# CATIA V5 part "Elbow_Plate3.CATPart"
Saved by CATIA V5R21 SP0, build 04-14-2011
Part number: Elbow_Plate3
Bounding box of the stored display mesh (mm): x -31.006 to 10.994, y -8.828 to -3.828, z 272.044 to 322.044
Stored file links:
  F:\教程\Robotic_Arm_Arduino_Kinect\机械臂CAD\Arm_Detailed_Design\Elbow_Plate3.CATPart
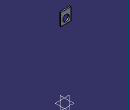
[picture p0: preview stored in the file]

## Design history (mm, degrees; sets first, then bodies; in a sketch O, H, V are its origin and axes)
Body1 (main body)
  DatumSurface1 to DatumSurface4
  Sketch1 on DatumSurface4, origin (0, -8.828, 0), H (-1, 0, 0), V (0, 0, 1)
    line L1 (-10.9938, 322.0436) -> (31.0062, 322.0436)
    line L2 (31.0062, 322.0436) -> (31.0062, 272.0436)
    line L3 (31.0062, 272.0436) -> (-10.9938, 272.0436)
    line L4 (-10.9938, 272.0436) -> (-10.9938, 322.0436)
    circle A1 centre (10.0062, 292.0436) radius 13
    point P5 (10.0062, 292.0436)
    length L1 = 42
    length L2 = 50
    radius A1 = 13
    distance P5 L1 = 30
    distance P5 L2 = 21
    horizontal: L1 H, L3 H
    vertical: L2 V, L4 V
  Pad1: profile Sketch1, direction (0, 1, 0), length 5
  Sketch2 on face of Pad1 from Sketch1.L2, origin (-31.0062, 0, 0), H (0, -1, 0), V (0, 0, 1)
    circle A1 centre (6.328, 307.0436) radius 1.25
    point P1 (6.328, 307.0436)
    circle A2 centre (6.328, 287.0436) radius 1.25
    point P2 (6.328, 287.0436)
    reference projected line E1 (8.828, 322.0436) -> (3.828, 322.0436) from edge [face of Pad1 from Sketch1.L1 | face of Pad1 from Sketch1.L2]
    reference projected line E2 (8.828, 272.0436) -> (8.828, 322.0436) from edge [start face of Pad1 | face of Pad1 from Sketch1.L2]
    reference projected line E3 (8.828, 272.0436) -> (8.828, 322.0436) from edge [start face of Pad1 | face of Pad1 from Sketch1.L2]
    reference projected line E4 (8.828, 272.0436) -> (3.828, 272.0436) from edge [face of Pad1 from Sketch1.L2 | face of Pad1 from Sketch1.L3]
    distance E1 P1 = 15
    radius A1 = 1.25
    distance E2 P1 = 2.5
    radius A2 = 1.25
    distance P2 E3 = 2.5
    distance P2 E4 = 15
  Pocket1: profile Sketch2, direction (1, 0, 0), length 4
  Sketch3 on face of Pad1 from Sketch1.L4, origin (10.9938, 0, 0), H (0, 1, 0), V (0, 0, 1)
    circle A1 centre (-6.5423, 307.4103) radius 1.3466
    point P1 (-6.5423, 307.4103)
    circle A2 centre (-6.328, 287.0436) radius 1.25
    point P2 (-6.328, 287.0436)
    reference projected line E1 (-3.828, 322.0436) -> (-3.828, 272.0436) from edge [face of Pad1 from Sketch1.L4 | end face of Pad1]
    reference projected line E2 (-8.828, 322.0436) -> (-3.828, 322.0436) from edge [face of Pad1 from Sketch1.L4 | face of Pad1 from Sketch1.L1]
    reference projected line E3 (-8.828, 272.0436) -> (-3.828, 272.0436) from edge [face of Pad1 from Sketch1.L3 | face of Pad1 from Sketch1.L4]
    reference projected line E4 (-8.828, 322.0436) -> (-8.828, 272.0436) from edge [start face of Pad1 | face of Pad1 from Sketch1.L4]
    radius A1 = 1.3466
    distance P1 E1 = 2.7143
    distance P1 E2 = 14.6333
    distance P2 E3 = 15
    distance P2 E4 = 2.5
    radius A2 = 1.25
  Pocket2: profile Sketch3, direction (-1, 0, 0), length 4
